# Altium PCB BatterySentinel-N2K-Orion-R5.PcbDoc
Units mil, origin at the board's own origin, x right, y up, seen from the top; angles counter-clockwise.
Board outline 2047.24 x 1417.32 mil, 2 copper layers (Top Layer, Bottom Layer), stack 62.992 mil thick; 37 components, 23 nets, 120 pads, 25 vias.
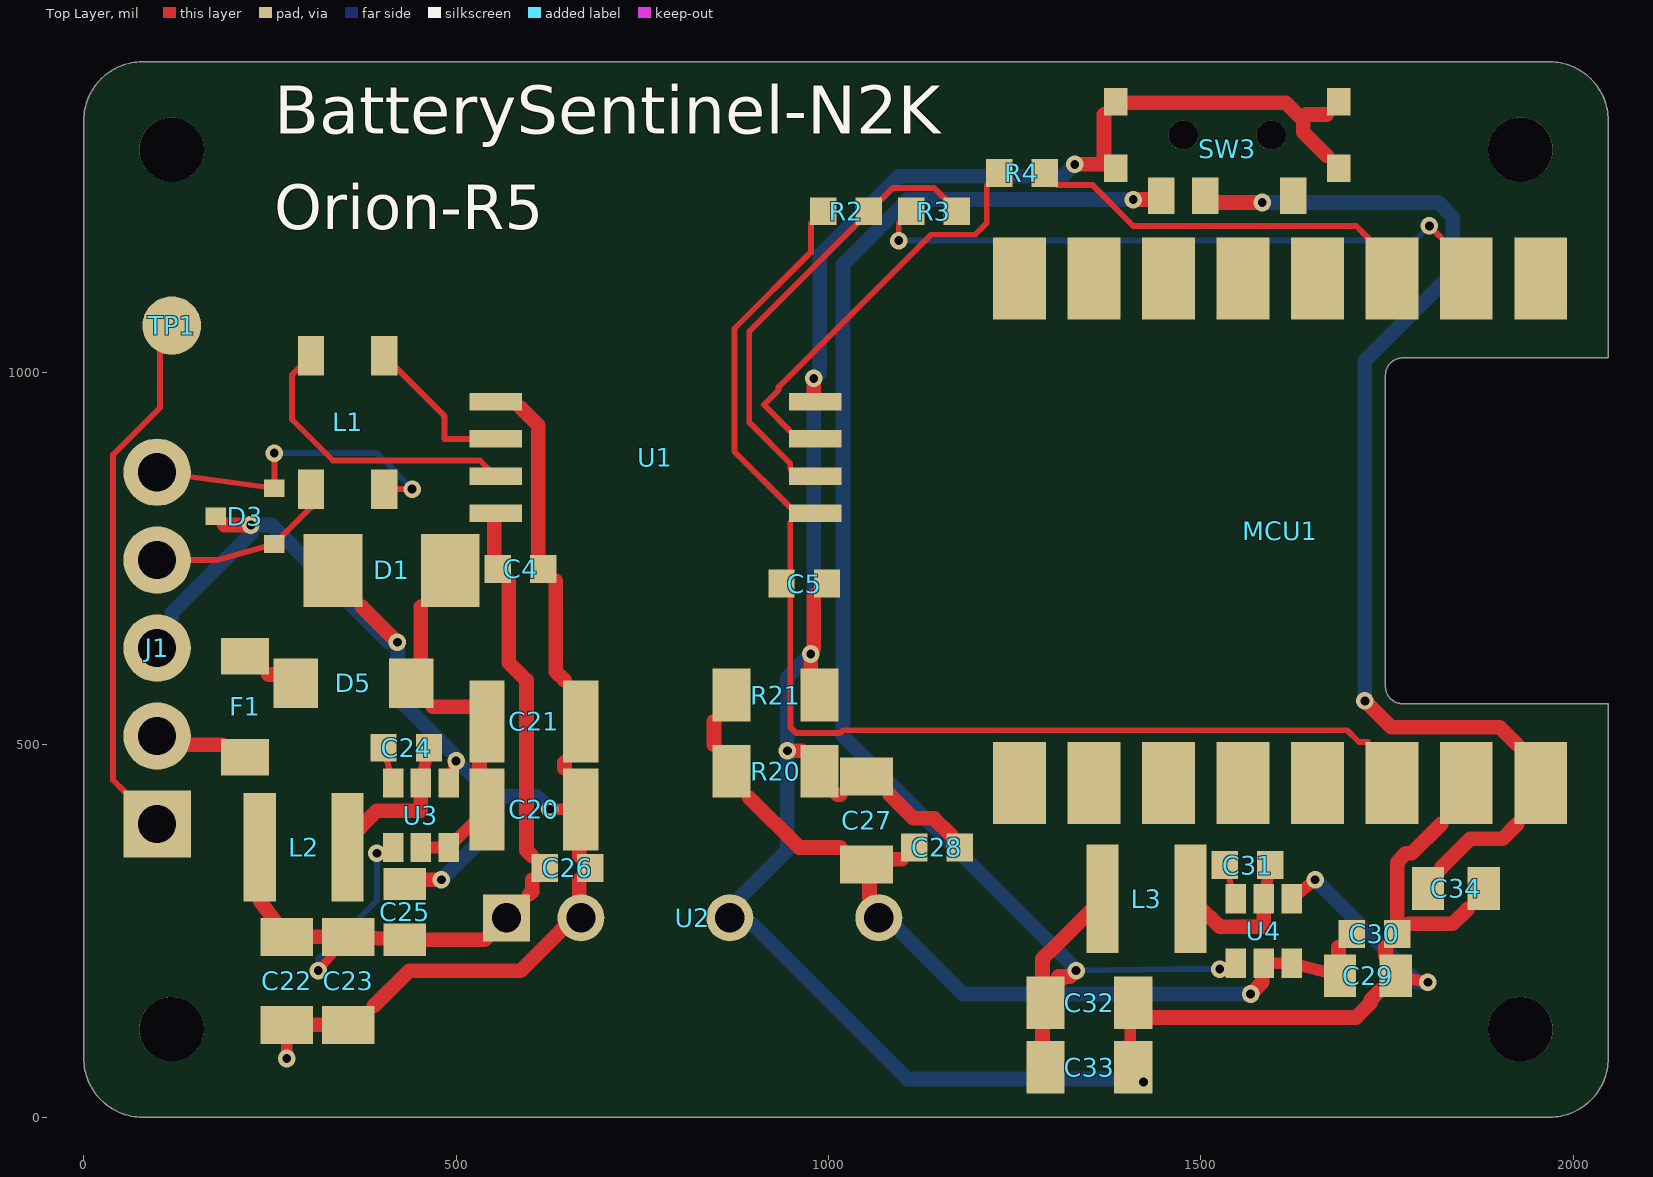
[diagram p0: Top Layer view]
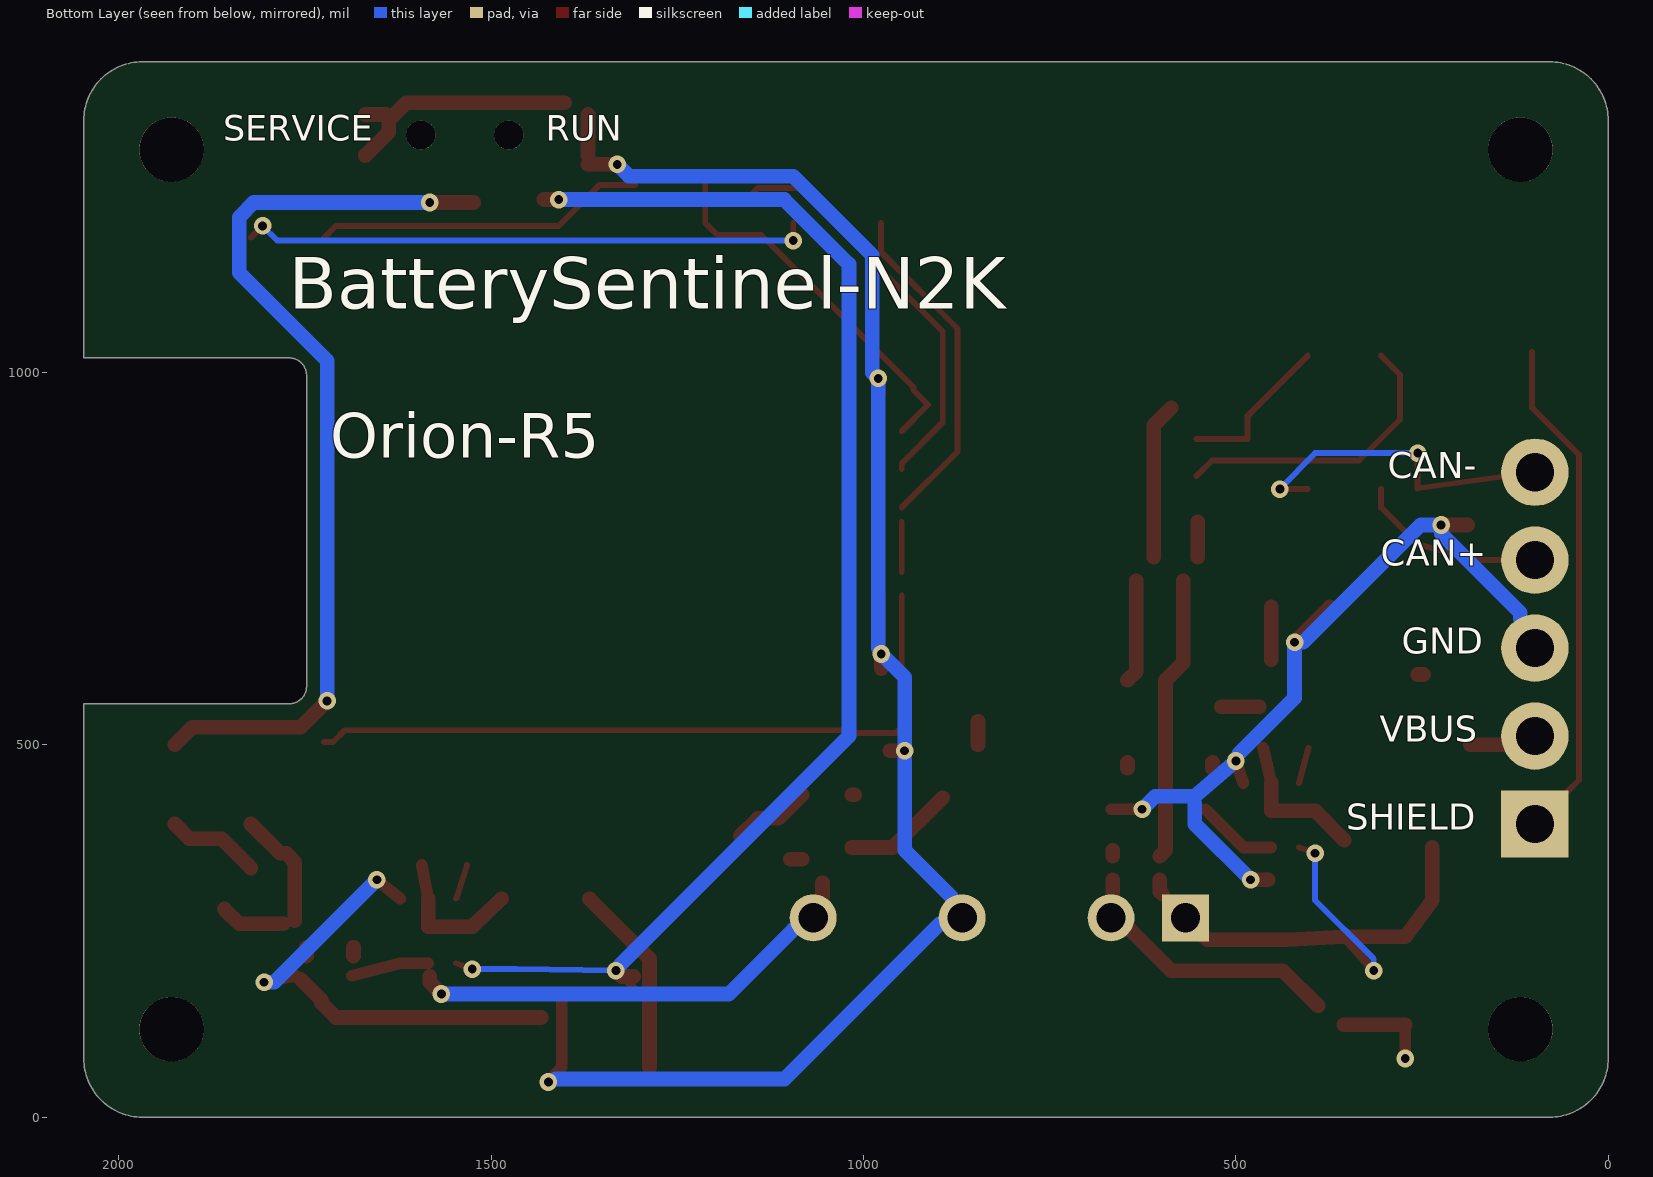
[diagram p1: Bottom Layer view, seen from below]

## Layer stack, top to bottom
Top Solder: solder mask 0.3937, Solder Resist, Dk 3.5
Top Layer: signal copper 1.378
Dielectric1: dielectric 60.2362, FR-4, Dk 4.3
Bottom Layer: signal copper 1.378
Bottom Solder: solder mask 0.3937, Solder Resist, Dk 3.5

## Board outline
78.74,0 74.88,0.09 71.02,0.38 67.19,0.85 63.38,1.51 59.61,2.36 55.88,3.39 52.21,4.6 48.61,5.99 45.07,7.56 41.62,9.3 38.26,11.2 34.99,13.27 31.83,15.5 28.79,17.87 25.86,20.4 23.06,23.06 20.4,25.86 17.87,28.79 15.5,31.83 13.27,34.99 11.2,38.26 9.3,41.62 7.56,45.07 5.99,48.61 4.6,52.21 3.39,55.88 2.36,59.61 1.51,63.38 0.85,67.19 0.38,71.02 0.09,74.88 0,78.74 0,1338.58 0.09,1342.45 0.38,1346.3 0.85,1350.14 1.51,1353.94 2.36,1357.71 3.39,1361.44 4.6,1365.11 5.99,1368.72 7.56,1372.25 9.3,1375.7 11.2,1379.06 13.27,1382.33 15.5,1385.49 17.87,1388.53 20.4,1391.46 23.06,1394.26 25.86,1396.93 28.79,1399.45 31.83,1401.83 34.99,1404.05 38.26,1406.12 41.62,1408.03 45.07,1409.76 48.61,1411.33 52.21,1412.72 55.88,1413.93 59.61,1414.96 63.38,1415.81 67.19,1416.47 71.02,1416.94 74.88,1417.23 78.74,1417.32 1968.5,1417.32 1972.37,1417.23 1976.22,1416.94 1980.06,1416.47 1983.87,1415.81 1987.64,1414.96 1991.36,1413.93 1995.03,1412.72 1998.64,1411.33 2002.17,1409.76 2005.62,1408.03 2008.98,1406.12 2012.25,1404.05 2015.41,1401.83 2018.46,1399.45 2021.38,1396.93 2024.18,1394.26 2026.85,1391.46 2029.37,1388.53 2031.75,1385.49 2033.97,1382.33 2036.04,1379.06 2037.95,1375.7 2039.68,1372.25 2041.25,1368.72 2042.64,1365.11 2043.85,1361.44 2044.88,1357.71 2045.73,1353.94 2046.39,1350.14 2046.86,1346.3 2047.15,1342.45 2047.24,1338.58 2047.24,1019.68 1771.65,1019.68 1770.49,1019.66 1769.34,1019.57 1768.19,1019.43 1767.05,1019.23 1765.91,1018.98 1764.8,1018.67 1763.7,1018.3 1762.61,1017.89 1761.55,1017.42 1760.52,1016.9 1759.51,1016.32 1758.53,1015.7 1757.58,1015.04 1756.67,1014.32 1755.79,1013.57 1754.95,1012.77 1754.15,1011.93 1753.39,1011.05 1752.68,1010.13 1752.01,1009.19 1751.39,1008.21 1750.82,1007.2 1750.3,1006.16 1749.83,1005.1 1749.41,1004.02 1749.05,1002.92 1748.74,1001.8 1748.49,1000.67 1748.29,999.53 1748.15,998.38 1748.06,997.22 1748.03,996.06 1748.03,578.74 1748.06,577.58 1748.15,576.42 1748.29,575.27 1748.49,574.13 1748.74,573 1749.05,571.88 1749.41,570.78 1749.83,569.7 1750.3,568.64 1750.82,567.6 1751.39,566.6 1752.01,565.62 1752.68,564.67 1753.39,563.75 1754.15,562.88 1754.95,562.04 1755.79,561.24 1756.67,560.48 1757.58,559.77 1758.53,559.1 1759.51,558.48 1760.52,557.91 1761.55,557.39 1762.61,556.92 1763.7,556.5 1764.8,556.14 1765.91,555.83 1767.05,555.57 1768.19,555.37 1769.34,555.23 1770.49,555.15 1771.65,555.12 2047.24,555.12 2047.24,78.74 2047.15,74.88 2046.86,71.02 2046.39,67.19 2045.73,63.38 2044.88,59.61 2043.85,55.88 2042.64,52.21 2041.25,48.61 2039.68,45.07 2037.95,41.62 2036.04,38.26 2033.97,34.99 2031.75,31.83 2029.37,28.79 2026.85,25.86 2024.18,23.06 2021.38,20.4 2018.46,17.87 2015.41,15.5 2012.25,13.27 2008.98,11.2 2005.62,9.3 2002.17,7.56 1998.64,5.99 1995.03,4.6 1991.36,3.39 1987.64,2.36 1983.87,1.51 1980.06,0.85 1976.22,0.38 1972.37,0.09 1968.5,0

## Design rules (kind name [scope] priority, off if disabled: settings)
AssemblyTestPointUsage [All] p0: scope1count=1 scope1_0_kind=Board scope1_0_value=Board scope2count=1 scope2_0_kind=Board scope2_0_value=Board commentlength=0
AssemblyTestpoint [All] p0: scope1count=1 scope1_0_kind=Board scope1_0_value=Board scope2count=1 scope2_0_kind=Board scope2_0_value=Board commentlength=0
BoardOutlineClearance BoardEdge_0_30mm [All] p0: scope1count=1 scope1_0_kind=Board scope1_0_value=Board scope2count=1 scope2_0_kind=Board scope2_0_value=Board commentlength=0 gap=11.81
BoardOutlineClearance BoardEdge_0_30mm [All] p1: gap=11.81 ignorepadtopadclearanceinfootprint=FALSE
Clearance [All] p0: scope1count=1 scope1_0_kind=Board scope1_0_value=Board scope2count=1 scope2_0_kind=Board scope2_0_value=Board commentlength=0 gap=5.91
Clearance Isolation_BUS_LOGIC [All] p0 off: scope1count=1 scope1_0_kind=Board scope1_0_value=Board scope2count=1 scope2_0_kind=Board scope2_0_value=Board commentlength=250 gap=125.98 // Protel DXP Scope 2 Expression Was: InNet('3V3_LOGIC') Or InNet('5V_ISO') Or InNet('5V_MODULE') Or InNet('5V_REG') Or InNet('BST_LOGIC') Or InNet('GND_LOGIC') Or InNet('GPIO6') Or InNet('GPIO7') Or InNet('RXD') Or InNet('SW_LOGIC') Or InNet('TXD')
Clearance Mounting_NPTH [All] p0 off: scope1count=1 scope1_0_kind=Board scope1_0_value=Board scope2count=1 scope2_0_kind=Board scope2_0_value=Board commentlength=120 gap=66.93 // Protel DXP Scope 1 Expression Was: IsPad And (HoleSize > 0) And (PadIsPlated = 'False') And (Not InComponent('SW3'))
Clearance Switch_Locating_Holes [All] p0 off: scope1count=1 scope1_0_kind=Board scope1_0_value=Board scope2count=1 scope2_0_kind=Board scope2_0_value=Board commentlength=114 gap=9.84 // Protel DXP Scope 1 Expression Was: IsPad And (HoleSize > 0) And (PadIsPlated = 'False') And InComponent('SW3')
Clearance Isolation_BUS_LOGIC [InNet('5V_BUS') Or InNet('BST_BUS') Or InNet('BUS_PROT') Or InNet('CANH') Or InNet('CANH_EXT') Or InNet('CANL') Or InNet('CANL_EXT') Or InNet('FUSED_IN') Or InNet('GND_BUS') Or InNet('NET_S') Or InNet('SHIELD') Or InNet('SW_BUS') vs InNet('3V3_LOGIC') Or InNet('5V_ISO') Or InNet('5V_MODULE') Or InNet('5V_REG') Or InNet('BST_LOGIC') Or InNet('GND_LOGIC') Or InNet('GPIO6') Or InNet('GPIO7') Or InNet('RXD') Or InNet('SW_LOGIC') Or InNet('TXD')] p1: gap=125.98 ignorepadtopadclearanceinfootprint=FALSE
Clearance Mounting_NPTH [IsPad And (HoleSize > 0) And (PadIsPlated = 'False') And (Not InComponent('SW3'))] p2: gap=66.93 ignorepadtopadclearanceinfootprint=FALSE
Clearance Switch_Locating_Holes [IsPad And (HoleSize > 0) And (PadIsPlated = 'False') And InComponent('SW3')] p3: gap=9.84 ignorepadtopadclearanceinfootprint=FALSE
Clearance [All] p4: gap=5.91 ignorepadtopadclearanceinfootprint=FALSE
ComponentClearance [All] p0: scope1count=1 scope1_0_kind=Board scope1_0_value=Board scope2count=1 scope2_0_kind=Board scope2_0_value=Board commentlength=0 gap=9.84 collisioncheckmode=3
ComponentClearance [All] p1: gap=9.84 collisioncheckmode=3 verticalgap=9.84 showdistances=FALSE
DiffPairsRouting [All] p0: scope1count=1 scope1_0_kind=Board scope1_0_value=Board scope2count=1 scope2_0_kind=Board scope2_0_value=Board commentlength=0
FabricationTestPointUsage [All] p0: scope1count=1 scope1_0_kind=Board scope1_0_value=Board scope2count=1 scope2_0_kind=Board scope2_0_value=Board commentlength=0 valid=0 allowmultiple=FALSE
FabricationTestpoint [All] p0: scope1count=1 scope1_0_kind=Board scope1_0_value=Board scope2count=1 scope2_0_kind=Board scope2_0_value=Board commentlength=0 side=3 testpointundercomponent=TRUE minsize=40 maxsize=100 preferedsize=60 minholesize=0 maxholesize=40 preferedholesize=32 testpointgrid=1
FanoutControl Fanout_BGA [All] p0 off: scope1count=1 scope1_0_kind=Board scope1_0_value=Board scope2count=1 scope2_0_kind=Board scope2_0_value=Board commentlength=69 // Protel DXP Scope 1 Expression Was: IsBGA   Fanout_BGA (Default Rule)
FanoutControl Fanout_LCC [All] p0 off: scope1count=1 scope1_0_kind=Board scope1_0_value=Board scope2count=1 scope2_0_kind=Board scope2_0_value=Board commentlength=69 // Protel DXP Scope 1 Expression Was: IsLCC   Fanout_LCC (Default Rule)
FanoutControl Fanout_SOIC [All] p0 off: scope1count=1 scope1_0_kind=Board scope1_0_value=Board scope2count=1 scope2_0_kind=Board scope2_0_value=Board commentlength=71 // Protel DXP Scope 1 Expression Was: IsSOIC   Fanout_SOIC (Default Rule)
FanoutControl Fanout_Small [All] p0 off: scope1count=1 scope1_0_kind=Board scope1_0_value=Board scope2count=1 scope2_0_kind=Board scope2_0_value=Board commentlength=84 // Protel DXP Scope 1 Expression Was: (CompPinCount < 5)   Fanout_Small (Default Rule)
FanoutControl Fanout_Default [All] p0: scope1count=1 scope1_0_kind=Board scope1_0_value=Board scope2count=1 scope2_0_kind=Board scope2_0_value=Board commentlength=30 // Fanout_Default (Default Rule)
Height [All] p0: scope1count=1 scope1_0_kind=Board scope1_0_value=Board scope2count=1 scope2_0_kind=Board scope2_0_value=Board commentlength=0
HoleSize [All] p0: scope1count=1 scope1_0_kind=Board scope1_0_value=Board scope2count=1 scope2_0_kind=Board scope2_0_value=Board commentlength=0 absolutevalues=TRUE maxlimit=248.03 minlimit=11.81 maxpercent=80.000 minpercent=20.000
HoleSize [All] p1: absolutevalues=TRUE maxlimit=248.03 minlimit=11.81 maxpercent=80.000 minpercent=20.000
HoleToHoleClearance [All] p0: scope1count=1 scope1_0_kind=Board scope1_0_value=Board scope2count=1 scope2_0_kind=Board scope2_0_value=Board commentlength=0
HoleToHoleClearance [All] p1: gap=9.84 allowstackedmicrovias=FALSE
LayerPairs [All] p0: scope1count=1 scope1_0_kind=Board scope1_0_value=Board scope2count=1 scope2_0_kind=Board scope2_0_value=Board commentlength=0 enforce=TRUE
MinimumAnnularRing PTH_AnnularRing [All] p0 off: scope1count=1 scope1_0_kind=Board scope1_0_value=Board scope2count=1 scope2_0_kind=Board scope2_0_value=Board commentlength=71 minimumring=7.09 // Protel DXP Scope 1 Expression Was: IsPad And (PadIsPlated = 'True')
MinimumAnnularRing Via_AnnularRing [All] p0 off: scope1count=1 scope1_0_kind=Board scope1_0_value=Board scope2count=1 scope2_0_kind=Board scope2_0_value=Board commentlength=44 minimumring=5.91 // Protel DXP Scope 1 Expression Was: IsVia
MinimumAnnularRing PTH_AnnularRing [IsPad And (PadIsPlated = 'True')] p1: minimumring=7.09
MinimumAnnularRing Via_AnnularRing [IsVia] p2: minimumring=5.91
MinimumSolderMaskSliver [All] p0: scope1count=1 scope1_0_kind=Board scope1_0_value=Board scope2count=1 scope2_0_kind=Board scope2_0_value=Board commentlength=0
MinimumSolderMaskSliver [All] p1: minsoldermaskwidth=3.94
NetAntennae [All] p0: scope1count=1 scope1_0_kind=Board scope1_0_value=Board scope2count=1 scope2_0_kind=Board scope2_0_value=Board commentlength=0
PasteMaskExpansion Paste_1to1 [All] p0: scope1count=1 scope1_0_kind=Board scope1_0_value=Board scope2count=1 scope2_0_kind=Board scope2_0_value=Board commentlength=0 expansion=0
PasteMaskExpansion Paste_1to1 [All] p1: expansion=0
PlaneClearance [All] p0: scope1count=1 scope1_0_kind=Board scope1_0_value=Board scope2count=1 scope2_0_kind=Board scope2_0_value=Board commentlength=0 clearance=20
PlaneConnect [All] p0: scope1count=1 scope1_0_kind=Board scope1_0_value=Board scope2count=1 scope2_0_kind=Board scope2_0_value=Board commentlength=0 planeconnectstyle=Relief reliefexpansion=20 reliefentries=4 reliefconductorwidth=10 reliefairgap=10
PolygonConnect [All] p0: scope1count=1 scope1_0_kind=Board scope1_0_value=Board scope2count=1 scope2_0_kind=Board scope2_0_value=Board commentlength=0 connectstyle=Relief reliefconductorwidth=10 reliefentries=4 polygonreliefangle="90 Angle"
PolygonConnect [All] p1: connectstyle=Relief reliefconductorwidth=10 reliefentries=4 polygonreliefangle="90 Angle" airgapwidth=10
RoutingCorners [All] p0: scope1count=1 scope1_0_kind=Board scope1_0_value=Board scope2count=1 scope2_0_kind=Board scope2_0_value=Board commentlength=0 cornerstyle=45-Degree minsetback=100 maxsetback=100
RoutingLayers [All] p0: scope1count=1 scope1_0_kind=Board scope1_0_value=Board scope2count=1 scope2_0_kind=Board scope2_0_value=Board commentlength=0 top layer=Automatic bottom layer=Automatic
RoutingPriority [All] p0: scope1count=1 scope1_0_kind=Board scope1_0_value=Board scope2count=1 scope2_0_kind=Board scope2_0_value=Board commentlength=0
RoutingTopology [All] p0: scope1count=1 scope1_0_kind=Board scope1_0_value=Board scope2count=1 scope2_0_kind=Board scope2_0_value=Board commentlength=0 topology=Shortest
RoutingVias [All] p0: scope1count=1 scope1_0_kind=Board scope1_0_value=Board scope2count=1 scope2_0_kind=Board scope2_0_value=Board commentlength=0 holewidth=11.81 width=23.62 viastyle="Through Hole" minholewidth=11.81 minwidth=23.62 maxholewidth=11.81 maxwidth=23.62
RoutingVias [All] p1: holewidth=11.81 width=23.62 viastyle="Through Hole" minholewidth=11.81 minwidth=23.62 maxholewidth=11.81 maxwidth=23.62
ShortCircuit [All] p0: scope1count=1 scope1_0_kind=Board scope1_0_value=Board scope2count=1 scope2_0_kind=Board scope2_0_value=Board commentlength=0 allowed=FALSE
SilkToBoardRegionClearance [All] p0: scope1count=1 scope1_0_kind=Board scope1_0_value=Board scope2count=1 scope2_0_kind=Board scope2_0_value=Board commentlength=0
SilkToSilkClearance SilkToSilk [All] p0: scope1count=1 scope1_0_kind=Board scope1_0_value=Board scope2count=1 scope2_0_kind=Board scope2_0_value=Board commentlength=0
SilkToSilkClearance SilkToSilk [All] p1: silktosilkclearance=3.94
SilkToSolderMaskClearance R5_Legend_Clearance [All] p0 off: scope1count=1 scope1_0_kind=Board scope1_0_value=Board scope2count=1 scope2_0_kind=Board scope2_0_value=Board commentlength=44 // Protel DXP Scope 1 Expression Was: IsPad
SilkToSolderMaskClearance R5_Legend_Clearance [IsPad] p1: minsilkscreentomaskgap=5.91 clearancetoexposedcopper=FALSE
SolderMaskExpansion TentedVias [All] p0 off: scope1count=1 scope1_0_kind=Board scope1_0_value=Board scope2count=1 scope2_0_kind=Board scope2_0_value=Board commentlength=44 expansion=-11.81 // Protel DXP Scope 1 Expression Was: IsVia
SolderMaskExpansion PadSolderMask [All] p0: scope1count=1 scope1_0_kind=Board scope1_0_value=Board scope2count=1 scope2_0_kind=Board scope2_0_value=Board commentlength=0 expansion=1.97
SolderMaskExpansion TentedVias [IsVia] p1: expansion=-11.81 istentingtop=TRUE
SolderMaskExpansion PadSolderMask [All] p2: expansion=1.97 istentingtop=FALSE
UnRoutedNet [All] p0: scope1count=1 scope1_0_kind=Board scope1_0_value=Board scope2count=1 scope2_0_kind=Board scope2_0_value=Board commentlength=0
UnpouredPolygon [All] p0: scope1count=1 scope1_0_kind=Board scope1_0_value=Board scope2count=1 scope2_0_kind=Board scope2_0_value=Board commentlength=0
Width [All] p0: scope1count=1 scope1_0_kind=Board scope1_0_value=Board scope2count=1 scope2_0_kind=Board scope2_0_value=Board commentlength=0 maxlimit=78.74 minlimit=7.87 preferedwidth=11.81
Width [All] p1: maxlimit=78.74 minlimit=7.87 preferedwidth=11.81
23 further rules are at their usual default settings.

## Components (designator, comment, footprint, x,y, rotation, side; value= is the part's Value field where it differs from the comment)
C4 "100nF 50V X7R" C0603#1 586.61,736.22 r0 top
C5 "100nF 50V X7R" C0603#2 967.52,716.54 r0 top
C20 "10uF 50V X7R" C1210#1 604.33,413.39 r0 top
C21 "10uF 50V X7R" C1210#2 604.33,531.5 r0 top
C22 "22uF 25V X5R" C1206 272.64,183.07 r270 top
C23 "22uF 25V X5R" C1206 355.31,183.07 r270 top
C24 "100nF 50V X7R" C0603#2 433.07,496.06 r0 top
C25 "10uF 25V X5R" C0805 431.1,275.59 r90 top
C26 "100nF 50V X7R" C0603#3 649.61,334.65 r0 top
C27 "22uF 25V X5R" C1206 1051.18,398.62 r90 top
C28 "100nF 50V X7R" C0603#4 1145.67,362.2 r0 top
C29 "10uF 25V X5R" C0805 1724.41,189.96 r0 top
C30 "100nF 50V X7R" C0603#2 1733.27,246.06 r0 top
C31 "100nF 50V X7R" C0603#3 1562.99,338.58 r0 top
C32 "22uF 25V X5R" C1206 1350.39,153.54 r0 top
C33 "22uF 25V X5R" C1206 1350.39,66.93 r0 top
C34 "10uF 25V X5R" C0805 1842.52,307.09 r0 top
D1 "SMBJ18A 600W" SMB 413.39,734.25 r180 top
D3 "PESD2CAN24T-Q" SOT23_NEXPERIA_REFLOW 216.54,807.09 r90 top
D5 "SS26 2A 60V" SMA 362.2,582.68 r180 top
F1 "T0.8A 63VDC" BOURNS_SF1206S 216.54,551.18 r90 top
J1 "NMEA Micro-C pigtail" PIGTAIL_5_P3_D1P3 98.43,629.92 r180 top
L1 "ACT45B-510-2P-TL003" ACT45B 354.33,933.07 r90 top
L2 "4.7uH" SUNLORD_SWPA4030 295.28,362.2 r180 top
L3 "4.7uH" SUNLORD_SWPA4030 1427.17,293.31 r180 top
MCU1 "" SUPERC3_B0FN4F6244_CAST16_SMD 1574.8,787.4 r270 top
R2 "10k 1% 0.1W" R0603 1023.62,1216.54 r0 top
R3 "33R" R0603 1141.73,1216.54 r0 top
R4 "33R" R0603 1259.84,1267.72 r0 top
R20 "150R 1% 0.5W" R1206 929.13,464.57 r0 top
R21 "150R 1% 0.5W" R1206 929.13,566.93 r0 top
SW3 "RUN / SERVICE" GSWITCH_MK12C02_G020 1535.43,1318.9 r0 top
TP1 "Shield / chassis pad" TESTPOINT_2MM 118.11,1062.99 r0 top
U1 "ISO1042DWV" SOIC8_DWV 767.72,885.83 r180 top
U2 "B0505S-3WR2" EVISUN_B0505S_3WR2 867.52,165.35 r0 top
U3 "AP63205WU-7" TSOT26_DIODES 452.76,405.51 r0 top
U4 "AP63205WU-7" TSOT26_DIODES 1584.65,250 r0 top

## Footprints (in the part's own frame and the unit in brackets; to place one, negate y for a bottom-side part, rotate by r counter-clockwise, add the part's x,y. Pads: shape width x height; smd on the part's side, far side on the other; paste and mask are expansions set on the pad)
ACT45B [mm] "TDK ACT45B recommended lands; windings 1-4 and 2-3"
  rect 1.35x0.9 smd: 1(-2.275,1.25) 2(-2.275,-1.25) 3(2.275,-1.25) 4(2.275,1.25)
BOURNS_SF1206S [mm] "Bourns SF-1206S recommended land pattern: total X span 4.7, inner gap 2.2, pad Y 1.65; maximum body envelope. No polarity."
  rect 1.25x1.65 smd: 1(-1.725,0)
  rect 1.25x1.65 smd mask+0: 2(1.725,0)
C0603#1 [mm] "IPC-style 0603 solder lands; selected MPN dimensions reviewed separately."
  rect 0.9x0.95 smd mask+0: 1(-0.775,0)
  rect 0.9x0.95 smd: 2(0.775,0)
C0603#2 [mm] "IPC-style 0603 solder lands; selected MPN dimensions reviewed separately."
  rect 0.9x0.95 smd: 1(-0.775,0) 2(0.775,0)
C0603#3 [mm] "IPC-style 0603 solder lands; selected MPN dimensions reviewed separately."
  rect 0.9x0.95 smd mask+0: 1(-0.775,0) 2(0.775,0)
C0603#4 [mm] "IPC-style 0603 solder lands; selected MPN dimensions reviewed separately."
  rect 0.9x0.95 smd: 1(-0.775,0)
  rect 0.9x0.95 smd mask+0: 2(0.775,0)
C0805 [mm] "IPC-style 0805 solder lands; selected MPN dimensions reviewed separately."
  rect 1.1x1.45 smd: 1(-0.95,0) 2(0.95,0)
C1206 [mm] "IPC-style 1206 solder lands; selected MPN dimensions reviewed separately."
  rect 1.3x1.8 smd: 1(-1.5,0) 2(1.5,0)
C1210#1 [mm] "Samsung CL32B106KBJNNNE body3.2x2.5mm, nominal1210 land pattern selected."
  rect 1.2x2.8 smd: 1(-1.6,0)
  rect 1.2x2.8 smd mask+0: 2(1.6,0)
C1210#2 [mm] "Samsung CL32B106KBJNNNE body3.2x2.5mm, nominal1210 land pattern selected."
  rect 1.2x2.8 smd: 1(-1.6,0) 2(1.6,0)
EVISUN_B0505S_3WR2 [mm] "EVISUN p4: nominal19.65x7x10.16mm, unspecified body tolerance+/-0.25mm, lead1 x=2.21 from body left, pitch1-2=2.54/2-4=5.08/4-6=5.08mm. Pin row .90mm from long body edge. Bottom view mirrored vertically to PCB TOP: row Y=+2.60mm. Finished holes1.00mm, annulus.30mm. Primary/secondary pad copper gap3.48mm."
  rect 1.6x1.6 hole 1 paste+0: 1(-7.615,2.6)
  round 1.6 hole 1 paste+0: 2(-5.075,2.6) 4(0.005,2.6) 6(5.085,2.6)
GSWITCH_MK12C02_G020 [mm] "All shell tabs tied only to GND_LOGIC. No paste in NPTH. Keep travel envelope clear. Pin numbers1/2/3 assigned left/common/right as manufacturer circuit A/B; mounting pads4-7 are local library assignments."
  rect 0.9x1.25 smd: 1(-2.25,-2.075) 2(-0.75,-2.075) 3(2.25,-2.075)
  rect 0.8x0.93 smd: 4(-3.8,1.135) 5(-3.8,-1.135) 6(3.8,1.135) 7(3.8,-1.135)
  round 1 hole 1 unplated paste+0 mask+0: ""(-1.5,0) ""(1.5,0)
PIGTAIL_5_P3_D1P3 [mm] "Designed carrier wire-solder interface, 3.0 pitch, 1.3 finished-hole target, 0.5 radial annulus. Pin numbering is logical NMEA: 1 shield, 2 NET-S, 3 NET-C, 4 CAN-H, 5 CAN-L. Cable and strain relief still require a physical selection."
  rect 2.3x2.3 hole 1.3 paste+0: 1(0,6)
  round 2.3 hole 1.3 paste+0: 2(0,3) 3(0,0) 4(0,-3) 5(0,-6)
R0603 [mm] "IPC-style 0603 solder lands; selected MPN dimensions reviewed separately."
  rect 0.9x0.95 smd: 1(-0.775,0) 2(0.775,0)
R1206 [mm] "IPC-style 1206 solder lands; selected MPN dimensions reviewed separately."
  rect 1.3x1.8 smd: 1(-1.5,0) 2(1.5,0)
SMA [mm] "MDD SS12-SS1200 Rev2025A3 p3 / SS22-SS2200 Rev2024A4 p3 suggested SMA pattern: pad1.52x1.68, centrepitch3.93, innergap2.41, totalX5.45mm. Maxbody4.5x2.8x2.45; pin1Kleft,2Aright. Visually checked selected C2480/C14238 PDFs."
  rect 1.52x1.68 smd: 1(-1.965,0)
  rect 1.52x1.68 smd mask+0: 2(1.965,0)
SMB [mm] "BORN SMBJ Series Rev2022-Jan-1-A p7 manufacturer pattern: pad2.0x2.5mm, innergap2.0mm, centres+/-2.0mm; maxbody4.7x3.9x2.5; pin1Kleft,2Aright. Visually checked selected C152104 PDF."
  rect 2x2.5 smd: 1(-2,0) 2(2,0)
SOIC8_DWV [mm] "TI DWV0008A manufacturer land pattern; pin 1 upper left"
  rect 1.8x0.6 smd mask+0: 1(-5.45,1.905) 2(-5.45,0.635) 3(-5.45,-0.635) 4(-5.45,-1.905)
  rect 1.8x0.6 smd: 5(5.45,-1.905) 6(5.45,-0.635) 7(5.45,0.635) 8(5.45,1.905)
SOT23_NEXPERIA_REFLOW [mm] "Nexperia SOT23 reflow footprint Fig10: 0.6 x 0.7 copper lands, 1.9 pin pitch and 2.0 row centres. Drawing is rotated 180 degrees to match existing top-view pin1 lower left, pin2 lower right, pin3 upper centre. Paste suggested0.5 x0.6, mask opening1.0 x1.0; set fabrication-specific expansions accordingly."
  rect 0.6x0.7 smd: 1(-0.95,-1) 2(0.95,-1) 3(0,1)
SUNLORD_SWPA4030 [mm] "Sunlord SWPA datasheet2025-05-08 p2 recommended SWPA4030S pattern: gap1.9, padwidth1.1, padheight3.7."
  rect 1.1x3.7 smd: 1(-1.5,0) 2(1.5,0)
SUPERC3_B0FN4F6244_CAST16_SMD [mm] "Selected ASIN B0FN4F6244. 16 SMD lands only, 2.8x1.8 at X +/-8.6; 2.54 pitch from Nologo reference. Outer castellation dimensions inferred from selected product photo, not a manufacturer land drawing. Manual perimeter soldering; no stencil paste, no carrier PTH, no pin headers. USB tails require the separate carrier cutout; see mechanical_interfaces."
  rect 2.8x1.8 smd paste-10: 0(8.6,-8.079) 1(8.6,-5.539) 2(8.6,-2.999) 3(8.6,-0.459) 3V3(8.6,4.621) 4(8.6,2.081) 5(-8.6,9.701) 5V(8.6,9.701) 6(-8.6,7.161) 7(-8.6,4.621) 8(-8.6,2.081) 9(-8.6,-0.459) 10(-8.6,-2.999) 20(-8.6,-5.539) 21(-8.6,-8.079) GND(8.6,7.161)
TESTPOINT_2MM [mm] "2 mm exposed top-copper test pad; no paste"
  round 2 smd paste-10: 1(0,0)
TSOT26_DIODES [mm] "Diodes DS41326 Rev3-2 p17 suggested TSOT26 copper: X=.70,Y=1.00,Y1=3.20 total span,C=.95. Top view: pin1 lower-left; pin4 upper-right."
  rect 0.7x1 smd: 1(-0.95,-1.1) 2(0,-1.1) 3(0.95,-1.1) 4(0.95,1.1) 5(0,1.1) 6(-0.95,1.1)

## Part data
C4: library part R5_C4_100nF, "100nF 16V X7R - generic specification; manufacturer/MPN not selected"
C5: library part R5_C5_100nF, "100nF 16V X7R - generic specification; manufacturer/MPN not selected"
C20: library part R5_C20_10uF
C21: library part R5_C21_10uF
C22: library part R5_C22_22uF
C23: library part R5_C23_22uF
C24: library part R5_C24_100nF
C25: library part R5_C25_10uF
C26: library part R5_C26_100nF
C27: library part R5_C27_22uF
C28: library part R5_C28_100nF
C29: library part R5_C29_10uF
C30: library part R5_C30_100nF
C31: library part R5_C31_100nF
C32: library part R5_C32_22uF
C33: library part R5_C33_22uF
C34: library part R5_C34_10uF, "10uF local module5V reservoir after RUN/SERVICE switch"
D1: library part R5_D1_SMBJ18A
D3: library part R5_D3_PESD2CAN24T_Q
D5: library part R5_D5_SS26
F1: library part R5_F1_T0.8A, "0.8 A slow-blow SMD ceramic fuse, 63 VDC, 50 A interrupt rating"
J1: library part R5_J1_NMEA, "Five direct wire-solder pads for a separately selected Micro-C cable; this is a PCB interface, not an invented connector MPN or face view"
L1: library part R5_L1_ACT45B_510_2P_TL003
L2: library part R5_L2_4.7uH
L3: library part R5_L3_4.7uH
MCU1: library part R5_MCU1_ESP32_C3, "User-selected C3 SuperMini; original onboard USB/BOOT/RESET; direct castellated solder mounting"
R2: library part R5_R2_10k, "10k - generic specification; manufacturer/MPN not selected"
R3: library part R5_R3_33R, "33R - generic specification; manufacturer/MPN not selected"
R4: library part R5_R4_33R, "33R - generic specification; manufacturer/MPN not selected"
R20: library part R5_R20_150R
R21: library part R5_R21_150R
SW3: library part R5_SW3_RUN, "Side-actuated SPDT service supply disconnect, 1A at6V, original SuperMini USB service"
TP1: library part R5_TP1_Shield, "Shield / chassis pad - generic specification; manufacturer/MPN not selected"
U1: library part R5_U1_ISO1042DWV
U2: library part R5_U2_B0505S_3WR2
U3: library part R5_U3_AP63205WU_7
U4: library part R5_U4_AP63205WU_7, "Isolated-side 5V buck / high-duty pass-through, feeding physical RUN/SERVICE disconnect"

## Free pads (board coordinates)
  round 86.61 hole 86.61 unplated paste+0 mask+0: ""(118.11,118.11) ""(118.11,1299.21) ""(1929.13,118.11) ""(1929.13,1299.21)

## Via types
v1: diameter 23.62, hole 11.81, Top Layer to Bottom Layer, tented both sides, 25 vias

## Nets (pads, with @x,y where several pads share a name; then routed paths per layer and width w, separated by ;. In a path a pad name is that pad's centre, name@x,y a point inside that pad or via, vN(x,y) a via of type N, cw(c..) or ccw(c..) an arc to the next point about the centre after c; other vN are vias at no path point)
3V3_LOGIC: C5.1 MCU1.3V3 R2.1 U1.1 | length 1486.4
  Top Layer w7.87: C5.1@948.82,700.79 948.82,523.62 956.69,515.75 1015.75,515.75 1019.68,519.68 1696.85,519.68 1712.6,503.94 1724.41,503.94 ; C5.1@948.82,732.28 U1.1@948.82,799.21 ; U1.1@948.82,818.9 874.02,893.7 874.02,1059.06 976.38,1161.42 R2.1@976.38,1200.79
5V_BUS: C4.1 C22.1 C23.1 C25.1 C26.1 L2.2 U1.8 U2.1 U3.1 | length 1165
  Top Layer w7.87: v1(393.7,354.33) U3.1
  Top Layer w11.81: v1(314.96,196.85) C23.1
  Top Layer w19.68: L2.2 236.22,291.34 C22.1 C23.1 C25.1 538.19,238.19 U2.1 ; C4.1@551.18,751.97 U1.8@551.18,799.21 ; C4.1@570.87,720.47 570.87,610.24 594.49,586.61 594.49,358.27 C26.1@602.36,350.39 ; 598.43,299.21 602.36,303.15 C26.1@602.36,318.9
  Bottom Layer w7.87: v1(314.96,196.85) 314.96,212.6 393.7,291.34 v1(393.7,354.33)
5V_ISO: C27.1 C28.1 C29.1 C30.1 R20.1 R21.1 U2.6 U4.2 U4.3 | length 871.5
  Top Layer w15.75: U4.2 U4.3 C29.1
  Top Layer w19.68: 846.46,500 R21.1@846.46,531.5 ; R20.1@893.7,429.13 960.63,362.2 1015.75,362.2 ; U2.6@1055.12,295.28 C27.1@1055.12,314.96 ; C27.1@1082.68,346.46 C28.1@1098.43,346.46 ; v1(1566.93,165.35) 1582.68,181.1 U4.2@1582.68,188.98 ; C29.1@1685.04,216.54 C30.1@1685.04,228.35
  Bottom Layer w19.68: U2.6@1094.49,251.97 1181.1,165.35 v1(1566.93,165.35)
5V_MODULE: C34.1 MCU1.5V SW3.2 | length 1377.7
  Top Layer w19.68: SW3.2@1523.62,1228.35 v1(1582.68,1228.35) ; v1(1720.47,559.06) 1755.91,523.62 1901.57,523.62 MCU1.5V@1925.2,500 ; C34.1@1822.83,334.65 1862.2,374.02 1905.51,374.02 MCU1.5V@1925.2,393.7
  Bottom Layer w19.68: v1(1582.68,1228.35) 1818.9,1228.35 1838.58,1208.66 1838.58,1133.86 1720.47,1015.75 v1(1720.47,559.06)
5V_REG: C32.1 C33.1 L3.2 SW3.1 U4.1 | length 2078.8
  Top Layer w7.87: v1(1525.59,198.82) U4.1
  Top Layer w9.84: C32.1@1287.4,153.54 v1(1332.68,196.85)
  Top Layer w19.68: C33.1@1287.4,66.93 1287.4,153.54 1287.4,212.6 1305.12,230.31 L3.2 ; 1309.06,188.98 1324.8,188.98 v1(1332.68,196.85) ; v1(1409.45,1232.28) SW3.1@1429.13,1232.28
  Bottom Layer w7.87: v1(1332.68,196.85) 1466.54,198.82 v1(1525.59,198.82)
  Bottom Layer w19.68: v1@1326.77,204.72 1019.68,511.81 1019.68,1145.67 1106.3,1232.28 v1(1409.45,1232.28)
BST_BUS: C24.1 U3.6 | length 48.9
  Top Layer w7.87: C24.1 U3.6
BST_LOGIC: C31.1 U4.6 | length 47.6
  Top Layer w7.87: C31.1 U4.6
BUS_PROT: C20.1 C21.1 D1.1 D5.1 U3.2 U3.3 | length 239.7
  Top Layer w15.75: U3.2 U3.3 C20.1
  Top Layer w19.68: D5.1@452.76,614.17 D1.1@452.76,685.04 ; D5.1@468.5,551.18 C21.1@519.68,551.18 ; C20.1@531.5,468.5 C21.1@531.5,476.38
CANH: L1.4 U1.7 | length 401.4
  Top Layer w7.87: L1.4 279.53,997.05 279.53,937.01 334.65,881.89 532.09,881.89 U1.7
CANH_EXT: D3.1 J1.4 L1.1 | length 254.7
  Top Layer w7.87: J1.4 179.13,748.03 D3.1 305.12,818.9 L1.1
CANL: L1.3 U1.6 | length 214.1
  Top Layer w7.87: L1.3 484.25,941.93 484.25,910.83 U1.6
CANL_EXT: D3.2 J1.5 L1.2 | length 448.9
  Top Layer w7.87: J1.5 D3.2 v1(255.91,891.73) ; L1.2 v1(440.94,843.5)
  Bottom Layer w7.87: v1(255.91,891.73) 393.7,891.73 v1(440.94,843.5)
FUSED_IN: D5.2 F1.2 | length 7.9
  Top Layer w19.68: F1.2@248.03,594.49 D5.2@255.91,594.49
GND_BUS: C4.2 C20.2 C21.2 C22.2 C23.2 C25.2 C26.2 D1.2 D3.3 J1.3 U1.5 U2.2 U3.4 | length 1882.6
  Top Layer w15.75: v1(272.64,78.74) C22.2 ; U3.4 v1(500,478.35) ; v1(625.98,413.39) C20.2
  Top Layer w19.68: D3.3@188.98,795.28 v1(224.41,795.28) ; C22.2 C23.2 ; D1.2@374.02,685.04 v1(421.26,637.8) ; 389.76,149.61 437.01,196.85 586.61,196.85 U2.2@641.73,251.97 ; C25.2@456.69,318.9 v1(480.31,318.9) ; U1.5@586.61,952.76 610.24,929.13 C4.2@610.24,751.97 ; C4.2@633.86,720.47 633.86,598.43 645.67,586.61 ; C20.2@645.67,468.5 C21.2@645.67,476.38 ; U2.2@665.35,295.28 C26.2@665.35,318.9 ; C26.2@665.35,350.39 C20.2@665.35,358.27
  Bottom Layer w19.68: J1.3@118.11,669.29 118.11,677.17 224.41,783.46 ; v1(224.41,795.28) 251.97,795.28 v1@409.45,637.8 ; v1(421.26,637.8) 421.26,562.99 v1@496.06,488.19 ; v1(480.31,318.9) 555.12,393.7 555.12,421.26 ; v1(500,478.35) 555.12,431.1 608.27,431.1 v1(625.98,413.39)
GND_LOGIC: C5.2 C27.2 C28.2 C29.2 C30.2 C32.2 C33.2 C34.2 MCU1.GND R20.2 R21.2 SW3.4 SW3.5 SW3.6 SW3.7 U1.4 U2.4 U4.4 | length 3547.3
  Top Layer w15.75: C32.2@1405.51,153.54 1405.51,66.93 v1(1423.23,47.24) ; U4.4 v1(1653.54,318.9) ; C29.2 v1(1805.12,181.1)
  Top Layer w19.68: v1(944.88,492.13) R20.2@964.57,492.13 ; 976.38,602.36 v1(976.38,622.05) ; v1@980.32,629.92 C5.2@980.32,700.79 ; U1.4@980.32,972.44 v1(980.32,992.13) ; R20.2@1011.81,433.07 1015.75,433.07 ; C27.2@1082.68,433.07 1114.17,401.57 1141.73,401.57 C28.2@1165.35,377.95 ; v1(1330.71,1279.53) 1370.08,1279.53 ; 1370.08,1291.34 1370.08,1346.46 ; SW3.4@1401.57,1362.2 1614.17,1362.2 1637.8,1338.58 1637.8,1322.83 1669.29,1291.34 ; C32.2@1433.07,133.86 1708.66,133.86 1728.35,153.54 1728.35,157.48 C29.2@1755.91,185.04 ; 1641.73,1346.46 1669.29,1346.46 ; C29.2@1748.03,216.54 C30.2@1748.03,228.35 ; C30.2@1763.78,263.78 1763.78,342.52 1775.59,354.33 1783.46,354.33 MCU1.GND@1822.83,393.7 ; C30.2@1779.53,259.84 1838.58,259.84 1858.27,279.53
  Bottom Layer w19.68: U2.4@881.89,295.28 944.88,358.27 944.88,480.31 ; U2.4@897.64,259.84 1106.3,51.18 v1@1413.39,51.18 ; v1(944.88,492.13) 944.88,590.55 v1(976.38,622.05) ; v1@980.32,629.92 v1(980.32,992.13) ; v1@988.19,1000 988.19,1157.48 1094.49,1263.78 1314.96,1263.78 v1(1330.71,1279.53) ; v1(1653.54,318.9) 1791.34,181.1 v1(1805.12,181.1)
GPIO6: MCU1.6 R3.1 | length 766.6
  Top Layer w7.87: v1(1094.49,1177.17) R3.1@1094.49,1200.79 ; v1(1807.09,1196.85) 1822.83,1181.1
  Bottom Layer w7.87: v1(1094.49,1177.17) 1787.4,1177.17 v1(1807.09,1196.85)
GPIO7: MCU1.7 R4.2 | length 446.7
  Top Layer w7.87: R4.2@1307.09,1251.97 1354.33,1251.97 1409.45,1196.85 1708.66,1196.85 1724.41,1181.1
NET_S: F1.1 J1.2 | length 43.3
  Top Layer w19.68: J1.2@141.73,500 F1.1@185.04,500
RXD: R4.1 U1.3 | length 503.9
  Top Layer w7.87: U1.3@948.82,921.26 913.39,956.69 933.07,976.38 933.07,980.32 1137.8,1185.04 1196.85,1185.04 1212.6,1200.79 R4.1@1212.6,1251.97
SHIELD: J1.1 TP1.1 | length 623.2
  Top Layer w7.87: J1.1@55.12,437.01 39.37,452.76 39.37,889.76 102.36,952.76 TP1.1@102.36,1027.56
SW_BUS: C24.2 L2.1 U3.5 | length 200.6
  Top Layer w15.75: U3.5 C24.2
  Top Layer w19.68: L2.1@354.33,372.05 393.7,411.42 452.76,411.42 U3.5
SW_LOGIC: C31.2 L3.1 U4.5 | length 196.9
  Top Layer w15.75: U4.5 C31.2
  Top Layer w19.68: L3.1 1525.59,255.91 1584.65,255.91 U4.5
TXD: R2.2 R3.2 U1.2 | length 513.5
  Top Layer w7.87: U1.2@948.82,870.08 948.82,877.95 893.7,933.07 893.7,1055.12 R2.2@1039.37,1200.79 ; R2.2@1070.87,1232.28 1086.61,1248.03 1141.73,1248.03 R3.2@1157.48,1232.28
pads on no net: MCU1.0 MCU1.1 MCU1.2 MCU1.3 MCU1.4 MCU1.5 MCU1.8 MCU1.9 MCU1.10 MCU1.20 MCU1.21 SW3. SW3.3

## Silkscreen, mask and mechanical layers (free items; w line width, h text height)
Top Overlay:
  text "BatterySentinel-N2K" at 255.91,1299.21 h110.24
  text "Orion-R5" at 255.91,1173.23 h102.36
Bottom Overlay:
  text "RUN" at 1427.17,1299.83 h59.06
  text "SERVICE" at 1860.2,1299.83 h59.06
  text "BatterySentinel-N2K" at 1771.65,1062.99 h118.11
  text "Orion-R5" at 1716.54,866.14 h102.36
  text "CAN-" at 296.35,846.92 h60
  text "CAN+" at 305.67,728.81 h60
  text "GND" at 277.18,610.7 h60
  text "VBUS" at 306.75,492.59 h60
  text "SHIELD" at 352.14,374.48 h60
Board outline:
  drawing of 332 lines, arcs and shapes, not listed
Isolation and RF planning:
  lines w3.94: 704.72,0 830.71,0 830.71,1417.32 704.72,1417.32 704.72,0 ; 1033.07,551.18 1358.27,551.18 1358.27,1023.62 1033.07,1023.62 1033.07,551.18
